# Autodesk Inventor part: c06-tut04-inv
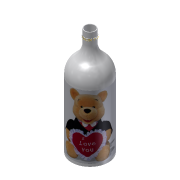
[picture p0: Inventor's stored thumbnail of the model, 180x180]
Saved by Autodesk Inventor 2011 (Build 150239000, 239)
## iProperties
Created: 2010-03
Part Number: c06-tut04-inv
Document SubType Name: Modeling
Designer: CADSoft
Density: 1 g/cm^3
Author: CADSoft
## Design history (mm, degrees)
sketch "Sketch1"
  geometry: 1 further point
sketch "Sketch2"
  geometry: L1 (0, 0)-(30, 0); L2 (30, 0)-(30, 113.567); L3 (8, 160)-(8, 180); L4 (0, -1)-(31, -1); L5 (31, -1)-(31, 113.567); L6 (9, 160)-(9, 180); L7 (9, 180)-(8, 180); L8 (0, 0)-(0, -1); L9 (0, -37.2)-(0, 216.2) reference; A1 r 30 centre (0, 113.567) between (30, 113.567) and (19, 136.784); A2 r 30 centre (38, 160) between (8, 160) and (19, 136.784); A3 r 31 centre (0, 113.567) between (31, 113.567) and (19.633, 137.558); A4 r 29 centre (38, 160) between (9, 160) and (19.633, 137.558)
  constraints: 16 end point, 8 point on circle, 4 centre point, 3 tangent, 2 vertical, 1 horizontal, 4 other
  dimensions: "d0" = 30 distance of L1.start L1.end; "d1" = 180 vertical distance of L1.end L3.end; "d2" = 30 radius of A1; "d3" = 30 radius of A2; "d4" = 20 distance of L3.start L3.end; "d7" = 8 distance from line of A1.centre L3; "d8" = 1 distance between parallel lines of L3 L6
revolve "Revolution1" sketch "Sketch2" stored, may be unused: angle "d9" = 90 deg
workplane "Work Plane1"
sketch "Sketch3"
  geometry: L1 (-21.993, 114.823)-(26.045, 114.823); L2 (26.045, 114.823)-(26.045, 111.018); L3 (26.045, 111.018)-(-21.993, 111.018); L4 (-21.993, 111.018)-(-21.993, 114.823); 1 further point
  constraints: 2 other
emboss "Emboss1" sketch "Sketch3" dims "d1" = 180, "d10" = 1, "d11" = 0
sketch "Sketch4"
  geometry: L1 (-79.426, 53.84)-(72.133, 53.84); L2 (72.133, 53.84)-(72.133, -52.9); L3 (72.133, -52.9)-(-79.426, -52.9); L4 (-79.426, -52.9)-(-79.426, 53.84); 1 further point; 1 other entity
  constraints: 2 other
feature "Decal1" sketch "Sketch4"
body "Solid1"
node "Image1"
